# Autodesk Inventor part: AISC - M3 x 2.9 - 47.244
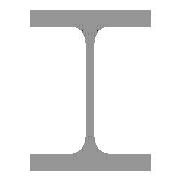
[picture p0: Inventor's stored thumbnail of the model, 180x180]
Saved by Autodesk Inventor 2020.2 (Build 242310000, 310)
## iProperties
Created: 2019-01
Part Number: AISC - M3 x 2.9 - 47.244
Material: Steel, Mild
Description: M-Shape
Document SubType Name: Modeling
Standard: ANSI
Designer: thira
Standards Organization: ANSI
Language: en-US
Size Designation: M3 x 2.9
Categories: <MemberInstance><Categories><Category DisplayName="Structural Shapes" InternalName="089c4875-fa83-4c05-b084-43b9cc11f5ed" Mnemonic="GRDR"><CategoryParameter Dis
Stock Number: M3 x 2.9
Density: 7.85 g/cm^3
Appearance: Semi-Polished
_CCFamilyMember: 14
_CCFamilyDisplayName: ANSI M - M-Shape — Sizes in parentheses have been withdrawn
_FrameMemberDoc: Frame Member File
_Version: 15.0.0
_GetPNFromCC: 1
G_L: 47.244 in
G_W: 2.250 in
G_H: 3.000 in
IsCustomPart: 1
Author: thira
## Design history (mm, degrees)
node "Start Plane"
node "End Plane"
sketch "Sketch"
  geometry: L1 (-28.575, -38.1)-(-28.575, -34.798); L2 (-28.575, -34.798)-(-10.541, -34.798); L3 (-1.143, -25.4)-(-1.143, 0); L4 (-1.143, 0)-(0, 0); L5 (0, 0)-(0, -38.1); L6 (0, -38.1)-(-28.575, -38.1); L7 (-60, 0)-(80, 0); L8 (0, -60)-(0, 80); L9 (28.575, -38.1)-(28.575, -34.798); L10 (28.575, -34.798)-(10.541, -34.798); L11 (0, -38.1)-(28.575, -38.1); L12 (1.143, -25.4)-(1.143, 0); L13 (1.143, 0)-(0, 0); L14 (-28.575, 38.1)-(-28.575, 34.798); L15 (0, 38.1)-(-28.575, 38.1); L16 (0, 38.1)-(28.575, 38.1); L17 (28.575, 34.798)-(10.541, 34.798); L18 (-28.575, 34.798)-(-10.541, 34.798); L19 (1.143, 25.4)-(1.143, 0); L20 (-1.143, 25.4)-(-1.143, 0); L21 (28.575, 38.1)-(28.575, 34.798); L22 (0, 108)-(0, -88) reference; L23 (-88, 0)-(108, 0) reference; A1 r 9.398 centre (-10.541, 25.4) between (-1.143, 25.4) and (-10.541, 34.798); A2 r 9.398 centre (10.541, 25.4) between (10.541, 34.798) and (1.143, 25.4); A3 r 9.398 centre (10.541, -25.4) between (1.143, -25.4) and (10.541, -34.798); A4 r 9.398 centre (-10.541, -25.4) between (-10.541, -34.798) and (-1.143, -25.4); 4 further points
  constraints: 42 end point, 11 symmetric about line, 8 point on circle, 8 point on line, 8 tangent, 4 centre point, 4 collinear, 4 parallel, 3 equal radius, 1 perpendicular, 1 vertical, 13 other
  dimensions: "d1" = 38.1 vertical distance of L1.start L3.end (= 0.5 x G_H); "d2" = 3.302 distance between parallel lines of L2 L6 (= G_T1); "d3" = 28.575 distance from line of L5.end L1 (= 0.5 x G_W); "d4" = 1.143 distance between parallel lines of L5 L3 (= 0.5 x G_T); "d13" = 9.398 radius of A1 (= G_IR)
extrude "Body" new body sketch "Sketch" stored distance "d5" = 1200 (= G_L); taper "d6" = 0 deg
node "Driven Length"
  sketch "Sketch4"
    geometry: L1 (0, 0)-(10, 0) reference
    constraints: 2 end point, 1 horizontal
  workplane "Work Plane3"
  sketch "Sketch5"
    geometry: L1 (-2, 0)-(12, 0) reference; L2 (-2, 1200)-(12, 1200) reference
    dimensions: "d15" = 1200 distance between parallel lines of L1 L2 (derived)
body "Solid1"
other parameters: "G_W" = 57.15 [user parameter; used in 1 equation term], "G_H" = 76.2 [user parameter; used in 1 equation term], "G_T" = 2.286 [user parameter; used in 1 equation term], "G_T1" = 3.302 [user parameter; used in 1 equation term], "G_IR" = 9.398 [user parameter; used in 1 equation term], "G_L" = 1200 (= d15) [user parameter; used in 1 equation term], "G_OFFSET_START" = 0 [user parameter; used in 1 equation term], "G_OFFSET_END" = 0 [user parameter; used in 1 equation term], "d11" = 0 (computed from G_OFFSET_START), "d12" = 1200 (= G_OFFSET_END + B_L), "B_L" = 1200 [user parameter; used in 1 equation term], "d14" = 90 deg
